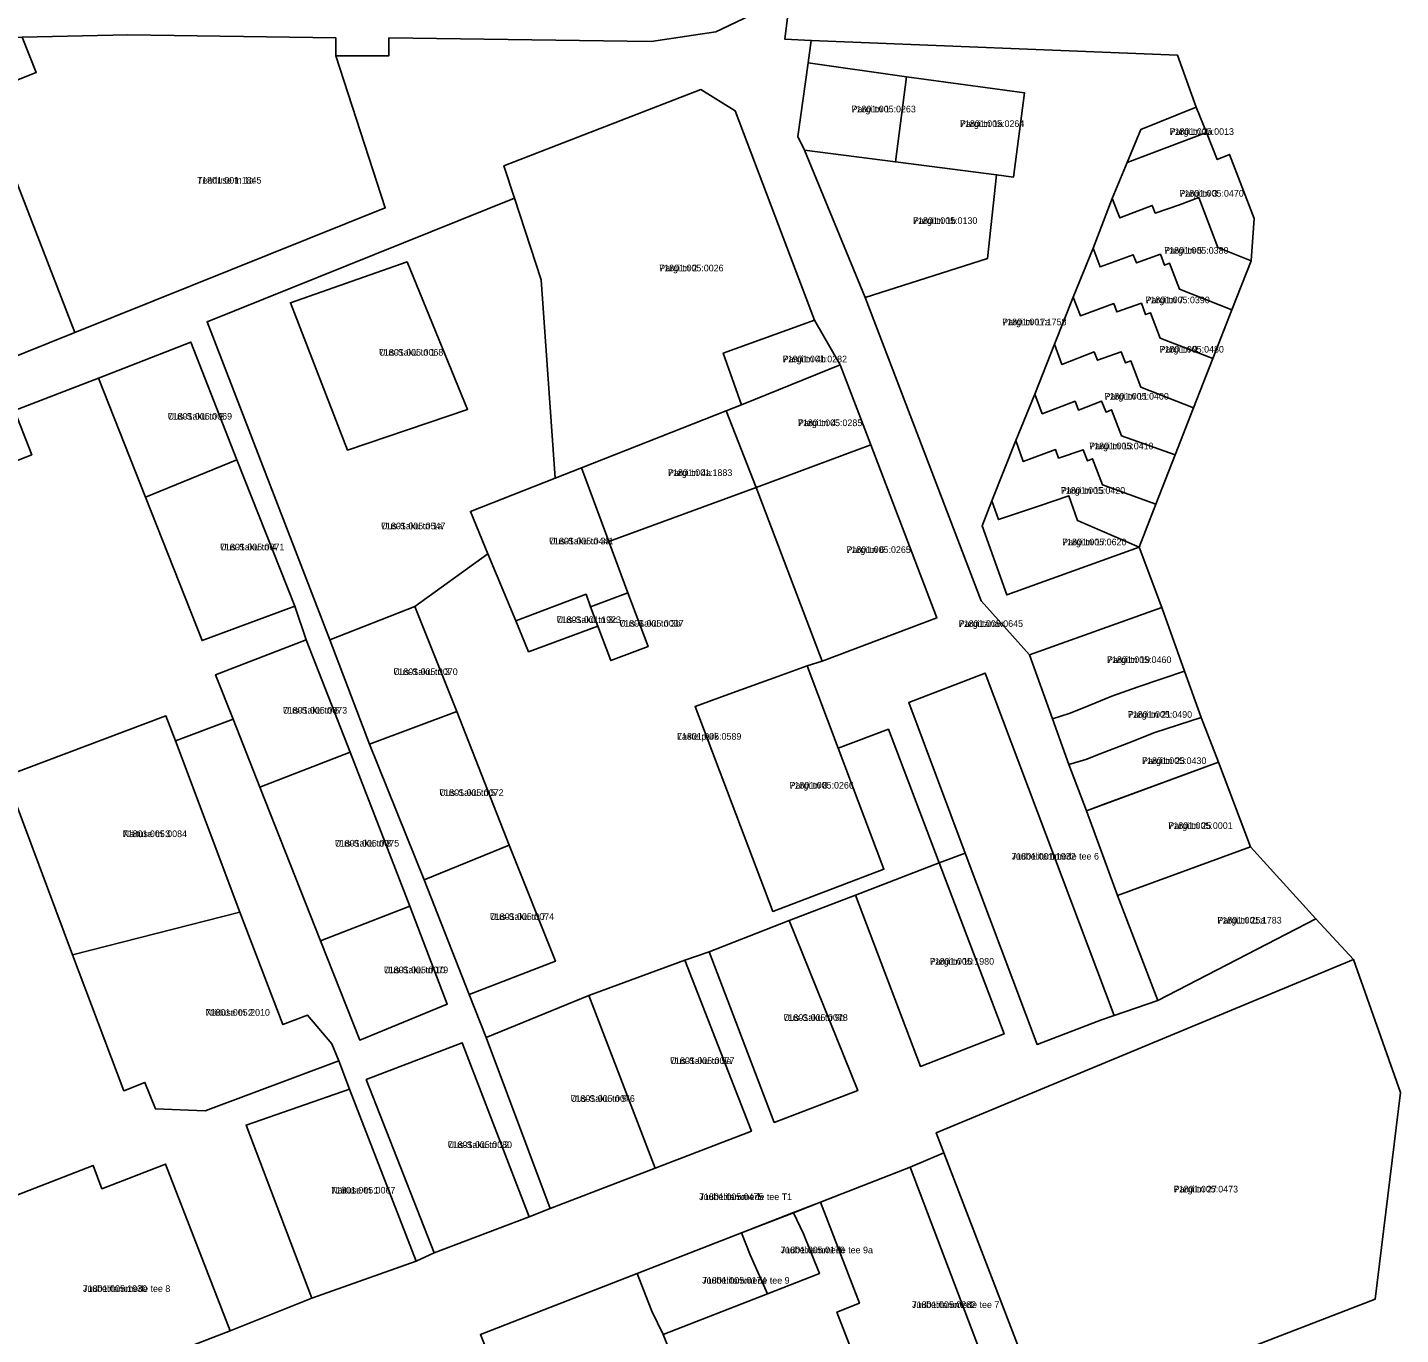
# Model space of a CAD drawing. Extents: x 529768 to 552006, y 6562269 to 6580975.
# Drawn here: x 537591.4 to 537901.1, y 6573473.5 to 6573768.4 of the extents above; entities that cross this region are included whole.
import ezdxf

# ---------------------------------------------------------------- set-up
doc = ezdxf.new("R2010")
doc.units = 0
for name, color, linetype in [('L_AADRESS', 7, 'Continuous'), ('PIIR', 7, 'Continuous'), ('TUNNUS', 7, 'Continuous')]:
    doc.layers.add(name, color=color, linetype=linetype)

msp = doc.modelspace()

# ---------------------------------------------------------------- linework, layer by layer
at = {"layer": 'PIIR'}
for points in [[(537765.19, 6573776.24), (537746.7, 6573767.42), (537732.1, 6573765.21), (537672.95, 6573766.02), (537672.95, 6573761.99), (537660.95, 6573761.99), (537660.96, 6573766.05), (537614.04, 6573766.76), (537590.23, 6573766.17), (537445.71, 6573764.43), (537422.16, 6573759.59), (537253.54, 6573749.28), (537102.2, 6573736.37), (537055.24, 6573734.52), (537012.74, 6573734.02), (537001.38, 6573734.57), (536984.82, 6573734.22), (536964.77, 6573736.87), (536937.07, 6573742.01), (536918.54, 6573746.68), (536890.37, 6573755.63), (536853.36, 6573771.71)], [(537483.1, 6573651.69), (537602.07, 6573699.55), (537672.12, 6573727.69), (537660.95, 6573761.99), (537672.95, 6573761.99), (537672.95, 6573766.02), (537732.1, 6573765.21), (537746.7, 6573767.42), (537765.19, 6573776.24)], [(537763.29, 6573774.23), (537762.26, 6573765.71), (537768.23, 6573765.48), (537767.51, 6573760.38), (537765.21, 6573743.79), (537766.66, 6573740.69), (537780.39, 6573707.43), (537806.51, 6573639.03), (537817.44, 6573626.81), (537822.62, 6573612.42), (537826.35, 6573602.1), (537830.28, 6573591.68), (537837.28, 6573572.53), (537846.4, 6573548.89), (537836.53, 6573545.5), (537807.42, 6573622.73), (537790.21, 6573616.1), (537802.97, 6573582.09), (537797.1, 6573579.89), (537785.62, 6573610.05), (537774.29, 6573605.78), (537767.27, 6573624.37), (537770.65, 6573625.44), (537796.56, 6573635.17), (537781.68, 6573674.2), (537774.76, 6573692.31), (537768.96, 6573702.37), (537751.03, 6573749.6), (537743.27, 6573754.36), (537698.9, 6573737.17), (537701.28, 6573729.9), (537631.92, 6573702), (537659.64, 6573630.26), (537668.55, 6573606.66), (537680.87, 6573576.07), (537691.08, 6573550.18), (537694.87, 6573540.52), (537709.35, 6573501.91), (537704.58, 6573500.04), (537689.48, 6573539.31), (537667.84, 6573531.03), (537683.13, 6573491.92), (537679.11, 6573490.07), (537664.09, 6573528.82), (537661.65, 6573535.22), (537660.07, 6573539.08), (537654.56, 6573545.55), (537649.04, 6573543.41), (537639.3, 6573568.77), (537624.77, 6573607.43), (537637.8, 6573612.33), (537643.83, 6573597), (537657.52, 6573562.35), (537666.38, 6573539.94), (537686.1, 6573548.06), (537677.65, 6573570.13), (537664.2, 6573604.92), (537654.31, 6573630.2), (537651.69, 6573637.79), (537638.66, 6573670.82), (537628.24, 6573697.39), (537607.47, 6573689.3), (537588.51, 6573681.95), (537592.37, 6573672), (537534.91, 6573649.54)], [(537853.55, 6573465.29), (537895.42, 6573481.49), (537901.14, 6573528.07), (537890.54, 6573558.08), (537882.06, 6573567.32), (537867.28, 6573583.55), (537860.06, 6573602.61), (537856.2, 6573612.73), (537852.43, 6573623.18), (537847.3, 6573637.55), (537842.2, 6573651.17), (537845.96, 6573660.8), (537850.32, 6573671.96), (537854.46, 6573682.55), (537858.83, 6573693.73), (537863.11, 6573704.7), (537867.43, 6573715.77), (537868.14, 6573725.25), (537862.57, 6573739.75), (537859.81, 6573738.59), (537857.39, 6573744.66), (537855.07, 6573750.41), (537850.86, 6573762.13), (537768.23, 6573765.48), (537762.26, 6573765.71), (537763.29, 6573774.23)], [(537534.91, 6573649.54), (537592.37, 6573672), (537588.51, 6573681.95), (537607.47, 6573689.3), (537618.05, 6573662.42), (537630.81, 6573630.06), (537651.69, 6573637.79), (537654.31, 6573630.2), (537633.84, 6573622.36), (537637.8, 6573612.33), (537624.77, 6573607.43), (537622.66, 6573613.05), (537586.5, 6573599.47), (537601.55, 6573559.18), (537613.17, 6573528.49), (537617.92, 6573530.36), (537620.26, 6573524.4), (537631.53, 6573524), (537661.65, 6573535.22), (537664.09, 6573528.82), (537640.71, 6573520.75), (537655.59, 6573481.71), (537637.12, 6573474.32), (537622.53, 6573511.95), (537608.22, 6573506.4), (537606.23, 6573511.65), (537584.85, 6573503.37)], [(537584.95, 6573454.28), (537637.12, 6573474.32), (537655.59, 6573481.71), (537679.11, 6573490.07), (537683.13, 6573491.92), (537704.58, 6573500.04), (537709.35, 6573501.91), (537732.98, 6573511), (537754.73, 6573519.38), (537739.71, 6573557.99), (537745.17, 6573559.81), (537759.88, 6573521.34), (537778.72, 6573528.54), (537763.25, 6573566.92), (537778.19, 6573572.66), (537792.84, 6573533.99), (537811.72, 6573541.32), (537797.1, 6573579.89), (537802.97, 6573582.09), (537819.15, 6573538.94), (537833.68, 6573544.52), (537836.53, 6573545.5), (537846.4, 6573548.89), (537882.06, 6573567.32), (537890.54, 6573558.08), (537796.41, 6573519.01), (537798.15, 6573514.47), (537790.54, 6573511.25), (537770.33, 6573503.38), (537764.22, 6573501.02), (537752.48, 6573496.44), (537728.92, 6573487.24), (537693.6, 6573473.49)], [(537811.47, 6573455.99), (537790.54, 6573511.25), (537798.15, 6573514.47), (537821.75, 6573453.03)], [(537736.31, 6573469.78), (537734.83, 6573473.5), (537758.38, 6573482.68), (537770.07, 6573487.24), (537766.49, 6573496.2), (537764.2, 6573500.99), (537770.33, 6573503.38), (537779.06, 6573480.57), (537773.99, 6573478.58), (537786.22, 6573446.98)]]:
    msp.add_lwpolyline(points, dxfattribs=at)
for points in [[(537593.38, 6573758.25), (537590.23, 6573766.17), (537614.04, 6573766.76), (537660.96, 6573766.05), (537660.95, 6573761.99), (537672.12, 6573727.69), (537602.07, 6573699.55), (537581.18, 6573753.45)], [(537438.72, 6573755.14), (537445.71, 6573764.43), (537590.23, 6573766.17), (537593.38, 6573758.25), (537581.18, 6573753.45), (537602.07, 6573699.55), (537483.1, 6573651.69), (537479.88, 6573650.4)], [(537847.3, 6573637.55), (537817.44, 6573626.81), (537806.51, 6573639.03), (537780.39, 6573707.43), (537807.99, 6573716.28), (537810.03, 6573735.17), (537813.83, 6573734.59), (537816.34, 6573753.61), (537789.68, 6573757.27), (537767.51, 6573760.38), (537768.23, 6573765.48), (537850.86, 6573762.13), (537855.07, 6573750.41), (537842.56, 6573745.38), (537839.48, 6573737.91), (537836.12, 6573729.77), (537831.77, 6573718.61), (537827.33, 6573707.53), (537823.09, 6573696.9), (537818.62, 6573685.63), (537814.38, 6573675.18), (537808.95, 6573661.56), (537806.73, 6573655.92), (537812.36, 6573640.38), (537842.2, 6573651.17)], [(537767.51, 6573760.38), (537789.68, 6573757.27), (537787.21, 6573738.07), (537766.66, 6573740.69), (537765.21, 6573743.79)], [(537789.68, 6573757.27), (537816.34, 6573753.61), (537813.83, 6573734.59), (537810.03, 6573735.17), (537787.21, 6573738.07)], [(537751.03, 6573749.6), (537768.96, 6573702.37), (537748.37, 6573694.91), (537752.45, 6573683.28), (537749.03, 6573681.92), (537716.36, 6573669.07), (537710.46, 6573666.7), (537707.32, 6573711.45), (537701.28, 6573729.9), (537698.9, 6573737.17), (537743.27, 6573754.36)], [(537857.39, 6573744.66), (537839.48, 6573737.91), (537842.56, 6573745.38), (537855.07, 6573750.41)], [(537857.39, 6573744.66), (537859.81, 6573738.59), (537862.57, 6573739.75), (537868.14, 6573725.25), (537867.43, 6573715.77), (537859.93, 6573718.71), (537855.61, 6573729.99), (537851.26, 6573728.36), (537845.8, 6573726.51), (537845.14, 6573728.23), (537837.81, 6573725.43), (537836.12, 6573729.77), (537839.48, 6573737.91)], [(537787.21, 6573738.07), (537810.03, 6573735.17), (537807.99, 6573716.28), (537780.39, 6573707.43), (537766.66, 6573740.69)], [(537631.92, 6573702), (537701.28, 6573729.9), (537707.32, 6573711.45), (537710.46, 6573666.7), (537691.32, 6573659.21), (537695.29, 6573649.64), (537678.8, 6573637.75), (537659.64, 6573630.26)], [(537863.11, 6573704.7), (537851.27, 6573709.33), (537849.04, 6573715.18), (537847.92, 6573714.75), (537846.97, 6573717.23), (537841.56, 6573715.25), (537840.86, 6573717.12), (537833.35, 6573714.37), (537831.77, 6573718.61), (537836.12, 6573729.77), (537837.81, 6573725.43), (537845.14, 6573728.23), (537845.8, 6573726.51), (537851.26, 6573728.36), (537855.61, 6573729.99), (537859.93, 6573718.71), (537867.43, 6573715.77)], [(537836.45, 6573706.08), (537828.93, 6573703.33), (537827.33, 6573707.53), (537831.77, 6573718.61), (537833.35, 6573714.37), (537840.86, 6573717.12), (537841.56, 6573715.25), (537846.97, 6573717.23), (537847.92, 6573714.75), (537849.04, 6573715.18), (537851.27, 6573709.33), (537863.11, 6573704.7), (537858.83, 6573693.73), (537846.89, 6573698.3), (537844.76, 6573704.04), (537843.62, 6573703.62), (537842.69, 6573706.15), (537837.15, 6573704.21)], [(537677.05, 6573715.48), (537690.7, 6573682.21), (537663.64, 6573673.03), (537650.73, 6573706.29)], [(537650.73, 6573706.29), (537663.64, 6573673.03), (537690.7, 6573682.21), (537677.05, 6573715.48)], [(537828.93, 6573703.33), (537836.45, 6573706.08), (537837.15, 6573704.21), (537842.69, 6573706.15), (537843.62, 6573703.62), (537844.76, 6573704.04), (537846.89, 6573698.3), (537858.83, 6573693.73), (537854.46, 6573682.55), (537842.54, 6573687.21), (537840.32, 6573693.16), (537839.11, 6573692.7), (537838.1, 6573695.21), (537832.78, 6573693.32), (537832.02, 6573695.18), (537824.74, 6573692.35), (537823.09, 6573696.9), (537827.33, 6573707.53)], [(537774.76, 6573692.31), (537752.45, 6573683.28), (537748.37, 6573694.91), (537768.96, 6573702.37)], [(537628.24, 6573697.39), (537638.66, 6573670.82), (537618.05, 6573662.42), (537607.47, 6573689.3)], [(537850.32, 6573671.96), (537838.22, 6573676.26), (537835.94, 6573682.13), (537834.72, 6573681.56), (537833.71, 6573684.07), (537828.47, 6573682.08), (537827.74, 6573684.07), (537820.31, 6573681.23), (537818.62, 6573685.63), (537823.09, 6573696.9), (537824.74, 6573692.35), (537832.02, 6573695.18), (537832.78, 6573693.32), (537838.1, 6573695.21), (537839.11, 6573692.7), (537840.32, 6573693.16), (537842.54, 6573687.21), (537854.46, 6573682.55)], [(537749.03, 6573681.92), (537752.45, 6573683.28), (537774.76, 6573692.31), (537781.68, 6573674.2), (537755.76, 6573664.57)], [(537823.33, 6573673.16), (537816.02, 6573670.44), (537814.38, 6573675.18), (537818.62, 6573685.63), (537820.31, 6573681.23), (537827.74, 6573684.07), (537828.47, 6573682.08), (537833.71, 6573684.07), (537834.72, 6573681.56), (537835.94, 6573682.13), (537838.22, 6573676.26), (537850.32, 6573671.96), (537845.96, 6573660.8), (537833.92, 6573665.19), (537831.65, 6573671.09), (537830.5, 6573670.61), (537829.54, 6573673.13), (537824, 6573671.25)], [(537716.36, 6573669.07), (537749.03, 6573681.92), (537755.76, 6573664.57), (537722.57, 6573652.45)], [(537755.76, 6573664.57), (537781.68, 6573674.2), (537796.56, 6573635.17), (537770.65, 6573625.44)], [(537810.44, 6573657.36), (537808.95, 6573661.56), (537814.38, 6573675.18), (537816.02, 6573670.44), (537823.33, 6573673.16), (537824, 6573671.25), (537829.54, 6573673.13), (537830.5, 6573670.61), (537831.65, 6573671.09), (537833.92, 6573665.19), (537845.96, 6573660.8), (537842.2, 6573651.17), (537828.24, 6573657.14), (537826.31, 6573662.72), (537819.67, 6573660.49)], [(537638.66, 6573670.82), (537651.69, 6573637.79), (537630.81, 6573630.06), (537618.05, 6573662.42)], [(537691.32, 6573659.21), (537710.46, 6573666.7), (537716.36, 6573669.07), (537722.57, 6573652.45), (537726.86, 6573640.86), (537718.43, 6573637.7), (537717.42, 6573640.51), (537701.56, 6573634.55), (537695.29, 6573649.64)], [(537678.8, 6573637.75), (537695.29, 6573649.64), (537701.56, 6573634.55), (537704.45, 6573627.53), (537720.07, 6573633.31), (537722.99, 6573625.53), (537731.42, 6573628.69), (537726.86, 6573640.86), (537722.57, 6573652.45), (537755.76, 6573664.57), (537770.65, 6573625.44), (537767.27, 6573624.37), (537760.68, 6573621.98), (537750.48, 6573618.28), (537742.02, 6573615.22), (537759.52, 6573568.97), (537784.6, 6573578.52), (537774.29, 6573605.78), (537785.62, 6573610.05), (537797.1, 6573579.89), (537778.19, 6573572.66), (537763.25, 6573566.92), (537745.17, 6573559.81), (537739.71, 6573557.99), (537718.02, 6573550), (537694.87, 6573540.52), (537691.08, 6573550.18), (537710.52, 6573557.71), (537700.09, 6573583.93), (537688.27, 6573614.03)], [(537806.73, 6573655.92), (537808.95, 6573661.56), (537810.44, 6573657.36), (537819.67, 6573660.49), (537826.31, 6573662.72), (537828.24, 6573657.14), (537842.2, 6573651.17), (537812.36, 6573640.38)], [(537704.45, 6573627.53), (537701.56, 6573634.55), (537717.42, 6573640.51), (537718.43, 6573637.7), (537720.07, 6573633.31)], [(537731.42, 6573628.69), (537722.99, 6573625.53), (537720.07, 6573633.31), (537718.43, 6573637.7), (537726.86, 6573640.86)], [(537678.8, 6573637.75), (537688.27, 6573614.03), (537668.55, 6573606.68), (537659.64, 6573630.26)], [(537852.43, 6573623.18), (537841.99, 6573619.66), (537835.98, 6573617.53), (537829.65, 6573614.9), (537826.38, 6573613.6), (537822.62, 6573612.42), (537817.44, 6573626.81), (537847.3, 6573637.55)], [(537654.31, 6573630.2), (537664.19, 6573604.92), (537643.84, 6573597), (537637.8, 6573612.33), (537633.84, 6573622.36)], [(537742.02, 6573615.22), (537750.48, 6573618.28), (537760.68, 6573621.98), (537767.27, 6573624.37), (537774.29, 6573605.78), (537784.6, 6573578.52), (537759.52, 6573568.97)], [(537802.97, 6573582.09), (537790.21, 6573616.1), (537807.42, 6573622.73), (537836.53, 6573545.5), (537833.68, 6573544.52), (537819.15, 6573538.94)], [(537833.38, 6573604.49), (537830.18, 6573603.2), (537826.35, 6573602.1), (537822.62, 6573612.42), (537826.38, 6573613.6), (537829.65, 6573614.9), (537835.98, 6573617.53), (537841.99, 6573619.66), (537852.43, 6573623.18), (537856.2, 6573612.73), (537845.71, 6573609.33), (537839.83, 6573606.96)], [(537622.66, 6573613.05), (537624.77, 6573607.43), (537639.3, 6573568.77), (537601.55, 6573559.18), (537586.5, 6573599.47)], [(537688.27, 6573614.03), (537700.09, 6573583.93), (537680.89, 6573576.08), (537668.55, 6573606.68)], [(537860.06, 6573602.61), (537830.28, 6573591.68), (537826.35, 6573602.1), (537830.18, 6573603.2), (537833.38, 6573604.49), (537839.83, 6573606.96), (537845.71, 6573609.33), (537856.2, 6573612.73)], [(537664.19, 6573604.92), (537677.65, 6573570.13), (537657.52, 6573562.35), (537643.84, 6573597)], [(537834.05, 6573593.06), (537843.69, 6573596.6), (537860.06, 6573602.61), (537867.28, 6573583.55), (537837.28, 6573572.53), (537830.28, 6573591.68)], [(537700.09, 6573583.93), (537710.52, 6573557.71), (537691.08, 6573550.18), (537680.89, 6573576.08)], [(537882.06, 6573567.32), (537846.4, 6573548.89), (537837.28, 6573572.53), (537867.28, 6573583.55)], [(537797.1, 6573579.89), (537811.72, 6573541.32), (537792.84, 6573533.99), (537778.19, 6573572.66)], [(537639.3, 6573568.77), (537649.04, 6573543.41), (537654.56, 6573545.55), (537660.07, 6573539.08), (537661.65, 6573535.22), (537631.53, 6573524), (537620.26, 6573524.4), (537617.92, 6573530.36), (537613.17, 6573528.49), (537601.55, 6573559.18)], [(537677.65, 6573570.13), (537686.1, 6573548.06), (537666.38, 6573539.94), (537657.52, 6573562.35)], [(537763.25, 6573566.92), (537778.72, 6573528.54), (537759.88, 6573521.34), (537745.17, 6573559.81)], [(537739.71, 6573557.99), (537754.73, 6573519.38), (537732.98, 6573511), (537718.02, 6573550)], [(537796.41, 6573519.01), (537890.54, 6573558.08), (537901.14, 6573528.07), (537895.42, 6573481.49), (537853.55, 6573465.29), (537829.73, 6573455.77), (537821.75, 6573453.03)], [(537718.02, 6573550), (537732.98, 6573511), (537709.35, 6573501.91), (537694.87, 6573540.52)], [(537689.48, 6573539.31), (537704.58, 6573500.04), (537683.13, 6573491.92), (537667.84, 6573531.03)], [(537664.09, 6573528.82), (537679.11, 6573490.07), (537655.59, 6573481.71), (537640.71, 6573520.75)], [(537584.85, 6573503.37), (537606.23, 6573511.65), (537608.22, 6573506.4), (537622.53, 6573511.95), (537637.12, 6573474.32), (537584.95, 6573454.28), (537568.9, 6573496.91)], [(537786.22, 6573446.98), (537773.99, 6573478.58), (537779.06, 6573480.57), (537770.33, 6573503.38), (537790.54, 6573511.25), (537811.47, 6573455.99), (537805.94, 6573453.89), (537799.95, 6573451.18), (537794.99, 6573449.68), (537794.36, 6573449.84), (537788.53, 6573447.88)], [(537758.38, 6573482.68), (537754.46, 6573491.48), (537752.48, 6573496.43), (537764.2, 6573500.99), (537766.49, 6573496.2), (537770.07, 6573487.24)], [(537734.83, 6573473.5), (537732.28, 6573478.76), (537730.9, 6573482.24), (537728.92, 6573487.24), (537752.48, 6573496.43), (537754.46, 6573491.48), (537758.38, 6573482.68)], [(537701.2, 6573456.06), (537699.15, 6573459.59), (537697.03, 6573464.9), (537693.6, 6573473.49), (537728.92, 6573487.24), (537730.9, 6573482.24), (537732.28, 6573478.76), (537734.83, 6573473.5), (537736.31, 6573469.78)]]:
    msp.add_lwpolyline(points, close=True, dxfattribs=at)

# ---------------------------------------------------------------- texts
at = {"layer": 'L_AADRESS'}
for s, p in [('Pargi tn 1', (537777.3, 6573749.23)), ('Pargi tn 1a', (537801.77, 6573745.93)), ('Pargi tn 3a', (537849.06, 6573744.16)), ('Teaduse tn 1a', (537629.69, 6573733.16)), ('Pargi tn 3', (537851.27, 6573730.21)), ('Pargi tn 1b', (537791.18, 6573724.06)), ('Pargi tn 5', (537847.83, 6573717.34)), ('Pargi tn 2', (537733.93, 6573713.36)), ('Pargi tn 7', (537843.6, 6573706.17)), ('Pargi tn 17a', (537811.29, 6573701.2)), ('Uus-Saku tn 1', (537670.71, 6573694.35)), ('Pargi tn 9', (537846.79, 6573695.04)), ('Pargi tn 4b', (537761.78, 6573692.83)), ('Pargi tn 11', (537834.37, 6573684.43)), ('Uus-Saku tn 2', (537623.06, 6573679.92)), ('Pargi tn 4', (537765.22, 6573678.44)), ('Pargi tn 13', (537830.92, 6573673.21)), ('Pargi tn 4a', (537735.9, 6573667.19)), ('Pargi tn 15', (537824.52, 6573663.18)), ('Uus-Saku tn 1a', (537671.19, 6573655.18)), ('Uus-Saku tn 4', (537634.87, 6573650.42)), ('Uus-Saku tn 3a', (537709.09, 6573651.77)), ('Pargi tn 17', (537824.81, 6573651.55)), ('Pargi tn 6', (537776.16, 6573649.83)), ('Uus-Saku tn 3c', (537710.79, 6573634.02)), ('Uus-Saku tn 3b', (537724.93, 6573633.2)), ('Pargi tänav', (537801.48, 6573633.15)), ('Uus-Saku tn 3', (537673.96, 6573622.28)), ('Pargi tn 19', (537834.94, 6573624.99)), ('Uus-Saku tn 6', (537649.02, 6573613.59)), ('Pargi tn 21', (537839.62, 6573612.64)), ('Laste park', (537737.95, 6573607.7)), ('Pargi tn 23', (537842.84, 6573602.21)), ('Uus-Saku tn 5', (537684.32, 6573595.02)), ('Pargi tn 8', (537763.31, 6573596.67)), ('Näituse tn 3', (537612.9, 6573585.72)), ('Pargi tn 25', (537848.77, 6573587.57)), ('Uus-Saku tn 8', (537660.75, 6573583.59)), ('Juubelitammede tee 6', (537813.37, 6573580.65)), ('Uus-Saku tn 7', (537695.71, 6573567.05)), ('Pargi tn 25a', (537859.82, 6573566.22)), ('Uus-Saku tn 10', (537671.81, 6573555.02)), ('Pargi tn 10', (537794.95, 6573556.94)), ('Näituse tn 2', (537631.6, 6573545.42)), ('Uus-Saku tn 9b', (537761.95, 6573544.27)), ('Uus-Saku tn 9a', (537736.38, 6573534.53)), ('Uus-Saku tn 9', (537713.92, 6573526)), ('Uus-Saku tn 12', (537686.21, 6573515.57)), ('Näituse tn 1', (537659.91, 6573505.31)), ('Pargi tn 27', (537849.98, 6573505.55)), ('Juubelitammede tee T1', (537742.93, 6573503.83)), ('Juubelitammede tee 9a', (537761.27, 6573491.83)), ('Juubelitammede tee 8', (537603.9, 6573483.12)), ('Juubelitammede tee 9', (537743.59, 6573484.96)), ('Juubelitammede tee 7', (537790.9, 6573479.49))]:
    msp.add_text(s, height=1.5, dxfattribs=at).set_placement(p)
at = {"layer": 'TUNNUS'}
for s, p in [('71801:005:0263', (537777.3, 6573749.23)), ('71801:005:0264', (537801.77, 6573745.93)), ('71801:005:0013', (537849.06, 6573744.16)), ('71801:001:1845', (537629.69, 6573733.16)), ('71801:005:0470', (537851.27, 6573730.21)), ('71801:005:0130', (537791.18, 6573724.06)), ('71801:005:0380', (537847.83, 6573717.34)), ('71801:005:0026', (537733.93, 6573713.36)), ('71801:005:0390', (537843.6, 6573706.17)), ('71801:001:1758', (537811.29, 6573701.2)), ('71801:005:0068', (537670.71, 6573694.35)), ('71801:005:0480', (537846.79, 6573695.04)), ('71901:001:0282', (537761.78, 6573692.83)), ('71801:005:0400', (537834.37, 6573684.43)), ('71801:005:0069', (537623.06, 6573679.92)), ('71801:005:0285', (537765.22, 6573678.44)), ('71801:005:0410', (537830.92, 6573673.21)), ('71801:001:1883', (537735.9, 6573667.19)), ('71801:005:0420', (537824.52, 6573663.18)), ('71801:005:0547', (537671.19, 6573655.18)), ('71801:005:0071', (537634.87, 6573650.42)), ('71801:005:0441', (537709.09, 6573651.77)), ('71801:005:0620', (537824.81, 6573651.55)), ('71801:005:0265', (537776.16, 6573649.83)), ('71801:001:1923', (537710.79, 6573634.02)), ('71801:005:0037', (537724.93, 6573633.2)), ('71801:005:0645', (537801.48, 6573633.15)), ('71801:005:0070', (537673.96, 6573622.28)), ('71801:005:0460', (537834.94, 6573624.99)), ('71801:005:0073', (537649.02, 6573613.59)), ('71801:005:0490', (537839.62, 6573612.64)), ('71801:005:0589', (537737.95, 6573607.7)), ('71801:005:0430', (537842.84, 6573602.21)), ('71801:005:0072', (537684.32, 6573595.02)), ('71801:005:0266', (537763.31, 6573596.67)), ('71801:005:0084', (537612.9, 6573585.72)), ('71801:005:0001', (537848.77, 6573587.57)), ('71801:005:0075', (537660.75, 6573583.59)), ('71801:001:1932', (537813.37, 6573580.65)), ('71801:005:0074', (537695.71, 6573567.05)), ('71801:001:1783', (537859.82, 6573566.22)), ('71801:005:0079', (537671.81, 6573555.02)), ('71801:005:1980', (537794.95, 6573556.94)), ('71801:005:2010', (537631.6, 6573545.42)), ('71801:005:0078', (537761.95, 6573544.27)), ('71801:005:0077', (537736.38, 6573534.53)), ('71801:005:0076', (537713.92, 6573526)), ('71801:005:0080', (537686.21, 6573515.57)), ('71801:005:0067', (537659.91, 6573505.31)), ('71801:005:0473', (537849.98, 6573505.55)), ('71801:005:0475', (537742.93, 6573503.83)), ('71801:005:0176', (537761.27, 6573491.83)), ('71801:005:1930', (537603.9, 6573483.12)), ('71801:005:0174', (537743.59, 6573484.96)), ('71801:005:0282', (537790.9, 6573479.49))]:
    msp.add_text(s, height=1.5, dxfattribs=at).set_placement(p)

doc.saveas('drawing.dxf')
